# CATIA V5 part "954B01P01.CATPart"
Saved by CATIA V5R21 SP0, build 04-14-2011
Part number: 954B01P01
Bounding box of the stored display mesh (mm): x -33.4 to 33.4, y -127 to 127, z -8 to 8
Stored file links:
  C:\Users\ALI OZGUN\Desktop\alhan\954B01P01.CATPart
  C:\Users\ALI OZGUN\Desktop\alhan\943B01P01.CATPart
  C:\Users\ALI OZGUN\Desktop\alhan\950B01P01.CATPart
  C:\Users\ALI OZGUN\Desktop\alhan\ALHAN_2INCI_PART.CATProduct
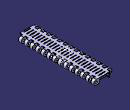
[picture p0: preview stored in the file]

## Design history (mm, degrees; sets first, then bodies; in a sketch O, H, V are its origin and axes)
Body1 (main body)
Body2
  Sketch1 on zx-plane, origin (0, 0, 0), H (-1, 0, 0), V (0, 0, 1)
    construction line L1 (25.4, 8) -> (25.4, -8)
    line L2 (25.4, -8) -> (-25.4, -8)
    construction line L3 (-25.4, -8) -> (-25.4, 8)
    line L4 (-25.4, 8) -> (25.4, 8)
    point P3 (-25.4, -8)
    arc A1 centre (25.4, 0) radius 8 from (25.4, 8) to (25.4, -8) cw
    arc A2 centre (-25.4, 0) radius 8 from (-25.4, 8) to (-25.4, -8) ccw
    point P7 (-25.4, -8)
    length L4 = 50.8
    length L3 = 16
    vertical: L1 V, L3 V
    horizontal: L2 H, L4 H
    equidistance: L1 L3 O, L2 L4 O
    tangency: A1 L2, A2 L4, A2 L2, L4 A1
    coincidence: P7 L2, P3 P7
  Pad1: profile Sketch1, direction (0, 1, 0), length 127, mirrored extent
  Sketch2 on zx-plane, origin (0, 0, 0), H (-1, 0, 0), V (0, 0, 1)
    circle A1 centre (25.4, 0) radius 3.15
    circle A2 centre (-25.4, 0) radius 3.15
  Pocket1: profile Sketch2, direction (0, -1, 0), length 204, mirrored extent
  Sketch3 on zx-plane, origin (0, 0, 0), H (-1, 0, 0), V (0, 0, 1)
    line L1 (0, 72) -> (0, 6.9718)
    point P1 (0, 72)
    reference projected line E1 (-25.4, -8) -> (25.4, -8) from edge [face of Pad1 from Sketch1.L2 | end face of Pad1]
    distance P1 E1 = 80
    coincidence: P1 V
    vertical: L1 V
  Sketch4, origin (0, -127, 0), H (1, 0, 0), V (0, 0, 1), geometry linked from another document
  Body3
    Solid1: solid without history
  Remove1: tool Body3
  RemoveFace1: RemoveFaces (face of Solid1; face of Solid1; face of Solid1; face of Pocket1 from Sketch2.A2; face of Pad1 from Sketch1.A2)
  Body4
    Solid2: solid without history
  Remove2: tool Body4
  Body5
    Solid3: solid without history
  Remove3: tool Body5
  Sketch5 on face of Pad1 from Sketch1.L4, origin (0, 0, 8), H (1, 0, 0), V (0, 1, 0)
    reference projected line E1 (-14.4, -124) -> (14.4, -124) from edge [face of Solid2 | face of Solid2]
    reference projected line E2 (-14.4, -112) -> (14.4, -112) from edge [face of Solid2 | face of Solid2]
    construction line L1 (10.1, -122.7) -> (-10.1, -122.7)
    point P5 (10.1, -122.7)
    line L2 (10.1, -124) -> (-10.1, -124)
    line L3 (-10.1, -121.4) -> (10.1, -121.4)
    arc A1 centre (-10.1, -122.7) radius 1.3 from (-10.1, -124) to (-10.1, -121.4) cw
    arc A2 centre (10.1, -122.7) radius 1.3 from (10.1, -121.4) to (10.1, -124) cw
    construction line L4 (10.1, -113.3) -> (-10.1, -113.3)
    point P11 (10.1, -113.3)
    line L5 (10.1, -114.6) -> (-10.1, -114.6)
    line L6 (-10.1, -112) -> (10.1, -112)
    arc A3 centre (-10.1, -113.3) radius 1.3 from (-10.1, -114.6) to (-10.1, -112) cw
    arc A4 centre (10.1, -113.3) radius 1.3 from (10.1, -112) to (10.1, -114.6) cw
    distance L1 L2 = 1.3
    distance L4 L5 = 1.3
    distance A2 A1 = 22.8
    distance A3 A4 = 22.8
    distance A4 V = 11.4
    distance P5 P11 H = 0
    horizontal: L1 H, L4 H
    tangency: A1 L2, A2 L2, A1 L3, A2 L3, A3 L5, A4 L5, A3 L6, A4 L6
    coincidence: E1 L2, E2 L6
  Pocket2: profile Sketch5, direction (0, 0, -1), length 10
  RectPattern1: of Pocket2, direction 1 instances 14, spacing 18.6, along yz-plane
Body6
  Sketch6 on face of Pad1 from Sketch1.L4, origin (0, 0, 8), H (1, 0, 0), V (0, 1, 0)
    construction line L1 (-7.5215, 124.4) -> (-15.1215, 124.4)
    line L2 (-7.5215, 125.6) -> (-15.1215, 125.6)
    line L3 (-15.1215, 123.2) -> (-7.5215, 123.2)
    arc A1 centre (-15.1215, 124.4) radius 1.2 from (-15.1215, 125.6) to (-15.1215, 123.2) ccw
    arc A2 centre (-7.5215, 124.4) radius 1.2 from (-7.5215, 123.2) to (-7.5215, 125.6) ccw
    construction line L4 (-7.5215, 120) -> (-15.1215, 120)
    line L5 (-7.5215, 121.2) -> (-15.1215, 121.2)
    line L6 (-15.1215, 118.8) -> (-7.5215, 118.8)
    arc A3 centre (-15.1215, 120) radius 1.2 from (-15.1215, 121.2) to (-15.1215, 118.8) ccw
    arc A4 centre (-7.5215, 120) radius 1.2 from (-7.5215, 118.8) to (-7.5215, 121.2) ccw
    construction line L7 (12.6215, 124.4) -> (7.5215, 124.4)
    line L8 (12.6215, 125.6) -> (7.5215, 125.6)
    line L9 (7.5215, 123.2) -> (12.6215, 123.2)
    arc A5 centre (7.5215, 124.4) radius 1.2 from (7.5215, 125.6) to (7.5215, 123.2) ccw
    arc A6 centre (12.6215, 124.4) radius 1.2 from (12.6215, 123.2) to (12.6215, 125.6) ccw
    construction line L10 (12.6215, 120) -> (7.5215, 120)
    line L11 (12.6215, 121.2) -> (7.5215, 121.2)
    line L12 (7.5215, 118.8) -> (12.6215, 118.8)
    arc A7 centre (7.5215, 120) radius 1.2 from (7.5215, 121.2) to (7.5215, 118.8) ccw
    arc A8 centre (12.6215, 120) radius 1.2 from (12.6215, 118.8) to (12.6215, 121.2) ccw
    axis line L13 (0, 140.1223) -> (0, 109.3492)
    construction line L14 (7.5215, 110.4) -> (16.1215, 110.4)
    construction line L15 (7.5215, 114.8) -> (16.1215, 114.8)
    construction line L16 (-13.1215, 110.4) -> (-7.5215, 110.4)
    construction line L17 (-13.1215, 114.8) -> (-7.5215, 114.8)
    line L18 (7.5215, 109.2) -> (16.1215, 109.2)
    line L19 (16.1215, 111.6) -> (7.5215, 111.6)
    arc A9 centre (16.1215, 110.4) radius 1.2 from (16.1215, 109.2) to (16.1215, 111.6) ccw
    arc A10 centre (7.5215, 110.4) radius 1.2 from (7.5215, 111.6) to (7.5215, 109.2) ccw
    line L20 (7.5215, 113.6) -> (16.1215, 113.6)
    line L21 (16.1215, 116) -> (7.5215, 116)
    arc A11 centre (16.1215, 114.8) radius 1.2 from (16.1215, 113.6) to (16.1215, 116) ccw
    arc A12 centre (7.5215, 114.8) radius 1.2 from (7.5215, 116) to (7.5215, 113.6) ccw
    line L22 (-13.1215, 109.2) -> (-7.5215, 109.2)
    line L23 (-7.5215, 111.6) -> (-13.1215, 111.6)
    arc A13 centre (-7.5215, 110.4) radius 1.2 from (-7.5215, 109.2) to (-7.5215, 111.6) ccw
    arc A14 centre (-13.1215, 110.4) radius 1.2 from (-13.1215, 111.6) to (-13.1215, 109.2) ccw
    line L24 (-13.1215, 113.6) -> (-7.5215, 113.6)
    line L25 (-7.5215, 116) -> (-13.1215, 116)
    arc A15 centre (-7.5215, 114.8) radius 1.2 from (-7.5215, 113.6) to (-7.5215, 116) ccw
    arc A16 centre (-13.1215, 114.8) radius 1.2 from (-13.1215, 116) to (-13.1215, 113.6) ccw
  Pad2: profile Sketch6, direction (0, 0, 1), length 10, mirrored extent
  RectPattern2: of the body so far, direction 1 instances 14, spacing 18, along yz-plane reversed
